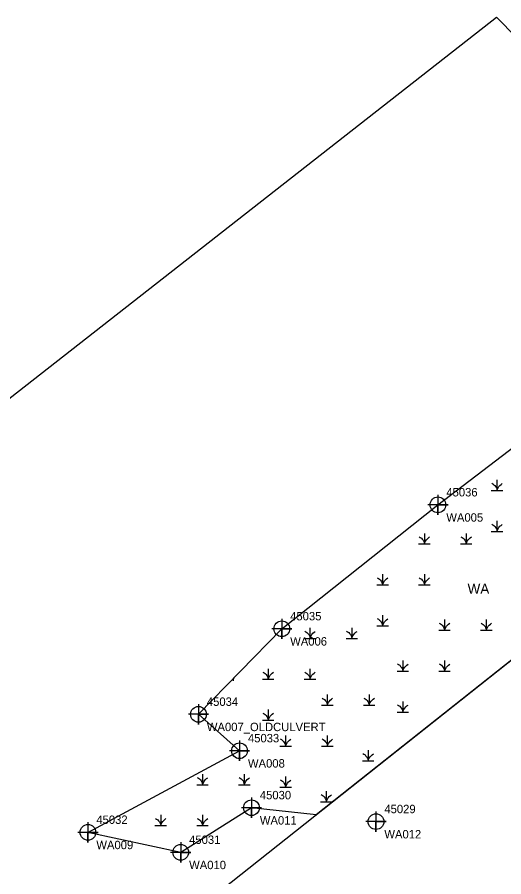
# Model space of a CAD drawing. Extents: x 1503676 to 1665494, y 654328 to 989038.
# Drawn here: x 1577550.8 to 1577695.6, y 654583.6 to 654839 of the extents above; entities that cross this region are included whole.
import ezdxf

# ---------------------------------------------------------------- set-up
doc = ezdxf.new("R2010")
doc.units = 0
for name, color, linetype in [('Default', 7, 'Continuous'), ('Level 14', 7, 'Continuous'), ('Level 17', 7, 'Continuous'), ('Level 2', 7, 'Continuous'), ('Level 25', 7, 'Continuous'), ('Level 28', 7, 'Continuous'), ('Level 3', 7, 'Continuous')]:
    doc.layers.add(name, color=color, linetype=linetype)

msp = doc.modelspace()

# ---------------------------------------------------------------- linework, layer by layer
at = {"layer": 'Default'}
msp.add_lwpolyline([(1577196.91, 654451.02), (1577693.44, 654839.04), (1577801.08, 654729.67), (1577293.27, 654327.76)], close=True, dxfattribs=at)
at = {"layer": 'Level 2'}
for points in [[(1577675.98, 654697.16), (1577675.98, 654691.16), (1577675.98, 654694.16), (1577678.98, 654694.16), (1577672.98, 654694.16)], [(1577629.53, 654660.34), (1577629.53, 654654.34), (1577629.53, 654657.34), (1577632.53, 654657.34), (1577626.53, 654657.34)], [(1577604.75, 654634.93), (1577604.75, 654628.93), (1577604.75, 654631.93), (1577607.75, 654631.93), (1577601.75, 654631.93)], [(1577616.97, 654624.1), (1577616.97, 654618.1), (1577616.97, 654621.1), (1577619.97, 654621.1), (1577613.97, 654621.1)], [(1577620.51, 654607.17), (1577620.51, 654601.17), (1577620.51, 654604.17), (1577623.51, 654604.17), (1577617.51, 654604.17)], [(1577657.55, 654603.05), (1577657.55, 654597.05), (1577657.55, 654600.05), (1577660.55, 654600.05), (1577654.55, 654600.05)], [(1577571.87, 654599.86), (1577571.87, 654593.86), (1577571.87, 654596.86), (1577574.87, 654596.86), (1577568.87, 654596.86)], [(1577599.47, 654593.92), (1577599.47, 654587.92), (1577599.47, 654590.92), (1577602.47, 654590.92), (1577596.47, 654590.92)]]:
    msp.add_lwpolyline(points, dxfattribs=at)
for centre in [(1577675.98, 654694.16), (1577629.53, 654657.34), (1577604.75, 654631.93), (1577616.97, 654621.1), (1577620.51, 654604.17), (1577657.55, 654600.05), (1577571.87, 654596.86), (1577599.47, 654590.92)]:
    msp.add_circle(centre, 2.34, dxfattribs=at)
at = {"layer": 'Level 28'}
for p, q in [((1577691.98, 654700.56), (1577692.33, 654700.37)), ((1577692.33, 654700.37), (1577692.65, 654700.15)), ((1577692.65, 654700.15), (1577692.92, 654699.86)), ((1577693.54, 654701.58), (1577693.54, 654698.42)), ((1577694.14, 654699.61), (1577694.44, 654699.94)), ((1577694.44, 654699.94), (1577694.76, 654700.23)), ((1577694.76, 654700.23), (1577695.11, 654700.5)), ((1577691.84, 654698.42), (1577695.27, 654698.42)), ((1577692.92, 654699.86), (1577693.17, 654699.53)), ((1577693.17, 654699.53), (1577693.36, 654699.18)), ((1577693.36, 654699.18), (1577693.46, 654698.8)), ((1577693.46, 654698.8), (1577693.54, 654698.42)), ((1577693.54, 654698.42), (1577693.71, 654698.83)), ((1577693.71, 654698.83), (1577693.9, 654699.23)), ((1577693.9, 654699.23), (1577694.14, 654699.61)), ((1577691.98, 654688.4), (1577692.33, 654688.21)), ((1577692.33, 654688.21), (1577692.65, 654687.99)), ((1577692.65, 654687.99), (1577692.92, 654687.7)), ((1577692.92, 654687.7), (1577693.17, 654687.37)), ((1577693.17, 654687.37), (1577693.36, 654687.02)), ((1577693.54, 654689.42), (1577693.54, 654686.27)), ((1577693.9, 654687.08), (1577694.14, 654687.45)), ((1577694.14, 654687.45), (1577694.44, 654687.78)), ((1577694.44, 654687.78), (1577694.76, 654688.07)), ((1577694.76, 654688.07), (1577695.11, 654688.34)), ((1577670.38, 654684.67), (1577670.73, 654684.48)), ((1577671.94, 654685.69), (1577671.94, 654682.53)), ((1577673.16, 654684.34), (1577673.51, 654684.61)), ((1577682.81, 654684.67), (1577683.16, 654684.48)), ((1577684.37, 654685.69), (1577684.37, 654682.53)), ((1577685.59, 654684.34), (1577685.94, 654684.61)), ((1577691.84, 654686.27), (1577695.27, 654686.27)), ((1577693.36, 654687.02), (1577693.46, 654686.64)), ((1577693.46, 654686.64), (1577693.54, 654686.27)), ((1577693.54, 654686.27), (1577693.71, 654686.67)), ((1577693.71, 654686.67), (1577693.9, 654687.08)), ((1577670.24, 654682.53), (1577673.67, 654682.53)), ((1577670.73, 654684.48), (1577671.05, 654684.26)), ((1577671.05, 654684.26), (1577671.32, 654683.96)), ((1577671.32, 654683.96), (1577671.57, 654683.64)), ((1577671.57, 654683.64), (1577671.76, 654683.29)), ((1577671.76, 654683.29), (1577671.86, 654682.91)), ((1577671.86, 654682.91), (1577671.94, 654682.53)), ((1577671.94, 654682.53), (1577672.11, 654682.94)), ((1577672.11, 654682.94), (1577672.3, 654683.34)), ((1577672.3, 654683.34), (1577672.54, 654683.72)), ((1577672.54, 654683.72), (1577672.84, 654684.04)), ((1577672.84, 654684.04), (1577673.16, 654684.34)), ((1577682.67, 654682.53), (1577686.1, 654682.53)), ((1577683.16, 654684.48), (1577683.48, 654684.26)), ((1577683.48, 654684.26), (1577683.75, 654683.96)), ((1577683.75, 654683.96), (1577684, 654683.64)), ((1577684, 654683.64), (1577684.18, 654683.29)), ((1577684.18, 654683.29), (1577684.29, 654682.91)), ((1577684.29, 654682.91), (1577684.37, 654682.53)), ((1577684.37, 654682.53), (1577684.54, 654682.94)), ((1577684.54, 654682.94), (1577684.72, 654683.34)), ((1577684.72, 654683.34), (1577684.97, 654683.72)), ((1577684.97, 654683.72), (1577685.26, 654684.04)), ((1577685.26, 654684.04), (1577685.59, 654684.34)), ((1577657.95, 654672.51), (1577658.3, 654672.32)), ((1577658.3, 654672.32), (1577658.62, 654672.1)), ((1577658.62, 654672.1), (1577658.89, 654671.8)), ((1577659.52, 654673.53), (1577659.52, 654670.37)), ((1577660.11, 654671.56), (1577660.41, 654671.89)), ((1577660.41, 654671.89), (1577660.73, 654672.18)), ((1577660.73, 654672.18), (1577661.08, 654672.45)), ((1577670.38, 654672.51), (1577670.73, 654672.32)), ((1577670.73, 654672.32), (1577671.05, 654672.1)), ((1577671.05, 654672.1), (1577671.32, 654671.8)), ((1577671.94, 654673.53), (1577671.94, 654670.37)), ((1577672.54, 654671.56), (1577672.84, 654671.89)), ((1577672.84, 654671.89), (1577673.16, 654672.18)), ((1577673.16, 654672.18), (1577673.51, 654672.45)), ((1577657.81, 654670.37), (1577661.24, 654670.37)), ((1577658.89, 654671.8), (1577659.14, 654671.48)), ((1577659.14, 654671.48), (1577659.33, 654671.13)), ((1577659.33, 654671.13), (1577659.43, 654670.75)), ((1577659.43, 654670.75), (1577659.52, 654670.37)), ((1577659.52, 654670.37), (1577659.68, 654670.78)), ((1577659.68, 654670.78), (1577659.87, 654671.18)), ((1577659.87, 654671.18), (1577660.11, 654671.56)), ((1577670.24, 654670.37), (1577673.67, 654670.37)), ((1577671.32, 654671.8), (1577671.57, 654671.48)), ((1577671.57, 654671.48), (1577671.76, 654671.13)), ((1577671.76, 654671.13), (1577671.86, 654670.75)), ((1577671.86, 654670.75), (1577671.94, 654670.37)), ((1577671.94, 654670.37), (1577672.11, 654670.78)), ((1577672.11, 654670.78), (1577672.3, 654671.18)), ((1577672.3, 654671.18), (1577672.54, 654671.56)), ((1577635.76, 654662.28), (1577635.78, 654662.18)), ((1577635.78, 654662.18), (1577635.85, 654662.36)), ((1577635.78, 654662.3), (1577635.78, 654662.18)), ((1577657.95, 654660.35), (1577658.3, 654660.16)), ((1577658.3, 654660.16), (1577658.62, 654659.94)), ((1577658.62, 654659.94), (1577658.89, 654659.65)), ((1577658.89, 654659.65), (1577659.14, 654659.32)), ((1577659.14, 654659.32), (1577659.33, 654658.97)), ((1577659.52, 654661.37), (1577659.52, 654658.21)), ((1577659.87, 654659.02), (1577660.11, 654659.4)), ((1577660.11, 654659.4), (1577660.41, 654659.73)), ((1577660.41, 654659.73), (1577660.73, 654660.02)), ((1577660.73, 654660.02), (1577661.08, 654660.29)), ((1577677.94, 654660.07), (1577677.94, 654656.91)), ((1577690.37, 654660.07), (1577690.37, 654656.91)), ((1577636.35, 654656.61), (1577636.7, 654656.43)), ((1577637.92, 654657.64), (1577637.92, 654654.48)), ((1577639.13, 654656.29), (1577639.48, 654656.56)), ((1577648.78, 654656.61), (1577649.13, 654656.43)), ((1577650.34, 654657.64), (1577650.34, 654654.48)), ((1577651.56, 654656.29), (1577651.91, 654656.56)), ((1577657.81, 654658.21), (1577661.24, 654658.21)), ((1577659.33, 654658.97), (1577659.43, 654658.59)), ((1577659.43, 654658.59), (1577659.52, 654658.21)), ((1577659.52, 654658.21), (1577659.68, 654658.62)), ((1577659.68, 654658.62), (1577659.87, 654659.02)), ((1577676.24, 654656.91), (1577679.67, 654656.91)), ((1577676.37, 654659.04), (1577676.73, 654658.85)), ((1577676.73, 654658.85), (1577677.05, 654658.63)), ((1577677.05, 654658.63), (1577677.32, 654658.34)), ((1577677.32, 654658.34), (1577677.56, 654658.01)), ((1577677.56, 654658.01), (1577677.75, 654657.66)), ((1577677.75, 654657.66), (1577677.86, 654657.28)), ((1577677.86, 654657.28), (1577677.94, 654656.91)), ((1577677.94, 654656.91), (1577678.1, 654657.31)), ((1577678.1, 654657.31), (1577678.29, 654657.72)), ((1577678.29, 654657.72), (1577678.53, 654658.09)), ((1577678.53, 654658.09), (1577678.83, 654658.42)), ((1577678.83, 654658.42), (1577679.16, 654658.72)), ((1577679.16, 654658.72), (1577679.51, 654658.99)), ((1577688.67, 654656.91), (1577692.1, 654656.91)), ((1577688.8, 654659.04), (1577689.15, 654658.85)), ((1577689.15, 654658.85), (1577689.48, 654658.63)), ((1577689.48, 654658.63), (1577689.75, 654658.34)), ((1577689.75, 654658.34), (1577689.99, 654658.01)), ((1577689.99, 654658.01), (1577690.18, 654657.66)), ((1577690.18, 654657.66), (1577690.29, 654657.28)), ((1577690.29, 654657.28), (1577690.37, 654656.91)), ((1577690.37, 654656.91), (1577690.53, 654657.31)), ((1577690.53, 654657.31), (1577690.72, 654657.72)), ((1577690.72, 654657.72), (1577690.96, 654658.09)), ((1577690.96, 654658.09), (1577691.26, 654658.42)), ((1577691.26, 654658.42), (1577691.58, 654658.72)), ((1577691.58, 654658.72), (1577691.94, 654658.99)), ((1577636.21, 654654.48), (1577639.64, 654654.48)), ((1577636.7, 654656.43), (1577637.02, 654656.21)), ((1577637.02, 654656.21), (1577637.29, 654655.91)), ((1577637.29, 654655.91), (1577637.54, 654655.59)), ((1577637.54, 654655.59), (1577637.73, 654655.24)), ((1577637.73, 654655.24), (1577637.83, 654654.86)), ((1577637.83, 654654.86), (1577637.92, 654654.48)), ((1577637.92, 654654.48), (1577638.08, 654654.89)), ((1577638.08, 654654.89), (1577638.27, 654655.29)), ((1577638.27, 654655.29), (1577638.51, 654655.67)), ((1577638.51, 654655.67), (1577638.81, 654655.99)), ((1577638.81, 654655.99), (1577639.13, 654656.29)), ((1577648.64, 654654.48), (1577652.07, 654654.48)), ((1577649.13, 654656.43), (1577649.45, 654656.21)), ((1577649.45, 654656.21), (1577649.72, 654655.91)), ((1577649.72, 654655.91), (1577649.97, 654655.59)), ((1577649.97, 654655.59), (1577650.16, 654655.24)), ((1577650.16, 654655.24), (1577650.26, 654654.86)), ((1577650.26, 654654.86), (1577650.34, 654654.48)), ((1577650.34, 654654.48), (1577650.51, 654654.89)), ((1577650.51, 654654.89), (1577650.7, 654655.29)), ((1577650.7, 654655.29), (1577650.94, 654655.67)), ((1577650.94, 654655.67), (1577651.24, 654655.99)), ((1577651.24, 654655.99), (1577651.56, 654656.29)), ((1577663.95, 654646.88), (1577664.3, 654646.69)), ((1577664.3, 654646.69), (1577664.62, 654646.48)), ((1577664.62, 654646.48), (1577664.89, 654646.18)), ((1577665.51, 654647.91), (1577665.51, 654644.75)), ((1577666.4, 654646.26), (1577666.73, 654646.56)), ((1577666.73, 654646.56), (1577667.08, 654646.83)), ((1577676.37, 654646.88), (1577676.73, 654646.69)), ((1577676.73, 654646.69), (1577677.05, 654646.48)), ((1577677.05, 654646.48), (1577677.32, 654646.18)), ((1577677.94, 654647.91), (1577677.94, 654644.75)), ((1577678.83, 654646.26), (1577679.16, 654646.56)), ((1577679.16, 654646.56), (1577679.51, 654646.83)), ((1577623.92, 654644.46), (1577624.27, 654644.27)), ((1577624.27, 654644.27), (1577624.6, 654644.05)), ((1577624.6, 654644.05), (1577624.87, 654643.75)), ((1577624.87, 654643.75), (1577625.11, 654643.43)), ((1577625.49, 654645.48), (1577625.49, 654642.32)), ((1577626.08, 654643.51), (1577626.38, 654643.83)), ((1577626.38, 654643.83), (1577626.7, 654644.13)), ((1577626.7, 654644.13), (1577627.05, 654644.4)), ((1577636.35, 654644.46), (1577636.7, 654644.27)), ((1577636.7, 654644.27), (1577637.02, 654644.05)), ((1577637.02, 654644.05), (1577637.29, 654643.75)), ((1577637.29, 654643.75), (1577637.54, 654643.43)), ((1577637.92, 654645.48), (1577637.92, 654642.32)), ((1577638.51, 654643.51), (1577638.81, 654643.83)), ((1577638.81, 654643.83), (1577639.13, 654644.13)), ((1577639.13, 654644.13), (1577639.48, 654644.4)), ((1577663.81, 654644.75), (1577667.24, 654644.75)), ((1577664.89, 654646.18), (1577665.13, 654645.85)), ((1577665.13, 654645.85), (1577665.32, 654645.5)), ((1577665.32, 654645.5), (1577665.43, 654645.13)), ((1577665.43, 654645.13), (1577665.51, 654644.75)), ((1577665.51, 654644.75), (1577665.67, 654645.15)), ((1577665.67, 654645.15), (1577665.86, 654645.56)), ((1577665.86, 654645.56), (1577666.11, 654645.94)), ((1577666.11, 654645.94), (1577666.4, 654646.26)), ((1577676.24, 654644.75), (1577679.67, 654644.75)), ((1577677.32, 654646.18), (1577677.56, 654645.85)), ((1577677.56, 654645.85), (1577677.75, 654645.5)), ((1577677.75, 654645.5), (1577677.86, 654645.13)), ((1577677.86, 654645.13), (1577677.94, 654644.75)), ((1577677.94, 654644.75), (1577678.1, 654645.15)), ((1577678.1, 654645.15), (1577678.29, 654645.56)), ((1577678.29, 654645.56), (1577678.53, 654645.94)), ((1577678.53, 654645.94), (1577678.83, 654646.26)), ((1577614.96, 654642.4), (1577615.06, 654641.91)), ((1577615.06, 654642.51), (1577615.06, 654641.91)), ((1577615.33, 654642.59), (1577615.51, 654642.97)), ((1577623.79, 654642.32), (1577627.21, 654642.32)), ((1577625.11, 654643.43), (1577625.3, 654643.08)), ((1577625.3, 654643.08), (1577625.41, 654642.7)), ((1577625.41, 654642.7), (1577625.49, 654642.32)), ((1577625.49, 654642.32), (1577625.65, 654642.73)), ((1577625.65, 654642.73), (1577625.84, 654643.13)), ((1577625.84, 654643.13), (1577626.08, 654643.51)), ((1577636.21, 654642.32), (1577639.64, 654642.32)), ((1577637.54, 654643.43), (1577637.73, 654643.08)), ((1577637.73, 654643.08), (1577637.83, 654642.7)), ((1577637.83, 654642.7), (1577637.92, 654642.32)), ((1577637.92, 654642.32), (1577638.08, 654642.73)), ((1577638.08, 654642.73), (1577638.27, 654643.13)), ((1577638.27, 654643.13), (1577638.51, 654643.51)), ((1577641.52, 654636.75), (1577641.87, 654636.57)), ((1577641.87, 654636.57), (1577642.19, 654636.35)), ((1577642.19, 654636.35), (1577642.46, 654636.05)), ((1577643.08, 654637.78), (1577643.08, 654634.62)), ((1577643.68, 654635.81), (1577643.97, 654636.13)), ((1577643.97, 654636.13), (1577644.3, 654636.43)), ((1577644.3, 654636.43), (1577644.65, 654636.7)), ((1577653.94, 654636.75), (1577654.3, 654636.57)), ((1577654.3, 654636.57), (1577654.62, 654636.35)), ((1577654.62, 654636.35), (1577654.89, 654636.05)), ((1577655.51, 654637.78), (1577655.51, 654634.62)), ((1577656.1, 654635.81), (1577656.4, 654636.13)), ((1577656.4, 654636.13), (1577656.73, 654636.43)), ((1577656.73, 654636.43), (1577657.08, 654636.7)), ((1577641.38, 654634.62), (1577644.81, 654634.62)), ((1577642.46, 654636.05), (1577642.7, 654635.73)), ((1577642.7, 654635.73), (1577642.89, 654635.38)), ((1577642.89, 654635.38), (1577643, 654635)), ((1577643, 654635), (1577643.08, 654634.62)), ((1577643.08, 654634.62), (1577643.24, 654635.03)), ((1577643.24, 654635.03), (1577643.43, 654635.43)), ((1577643.43, 654635.43), (1577643.68, 654635.81)), ((1577653.81, 654634.62), (1577657.24, 654634.62)), ((1577654.89, 654636.05), (1577655.13, 654635.73)), ((1577655.13, 654635.73), (1577655.32, 654635.38)), ((1577655.32, 654635.38), (1577655.43, 654635)), ((1577655.43, 654635), (1577655.51, 654634.62)), ((1577655.51, 654634.62), (1577655.67, 654635.03)), ((1577655.67, 654635.03), (1577655.86, 654635.43)), ((1577655.86, 654635.43), (1577656.1, 654635.81)), ((1577663.95, 654634.72), (1577664.3, 654634.53)), ((1577664.3, 654634.53), (1577664.62, 654634.32)), ((1577664.62, 654634.32), (1577664.89, 654634.02)), ((1577664.89, 654634.02), (1577665.13, 654633.7)), ((1577665.13, 654633.7), (1577665.32, 654633.34)), ((1577665.51, 654635.75), (1577665.51, 654632.59)), ((1577665.86, 654633.4), (1577666.11, 654633.78)), ((1577666.11, 654633.78), (1577666.4, 654634.1)), ((1577666.4, 654634.1), (1577666.73, 654634.4)), ((1577666.73, 654634.4), (1577667.08, 654634.67)), ((1577623.92, 654632.3), (1577624.27, 654632.11)), ((1577624.27, 654632.11), (1577624.6, 654631.89)), ((1577624.6, 654631.89), (1577624.87, 654631.59)), ((1577624.87, 654631.59), (1577625.11, 654631.27)), ((1577625.11, 654631.27), (1577625.3, 654630.92)), ((1577625.49, 654633.32), (1577625.49, 654630.16)), ((1577625.65, 654630.57), (1577625.84, 654630.97)), ((1577625.84, 654630.97), (1577626.08, 654631.35)), ((1577626.08, 654631.35), (1577626.38, 654631.68)), ((1577626.38, 654631.68), (1577626.7, 654631.97)), ((1577626.7, 654631.97), (1577627.05, 654632.24)), ((1577663.81, 654632.59), (1577667.24, 654632.59)), ((1577665.32, 654633.34), (1577665.43, 654632.97)), ((1577665.43, 654632.97), (1577665.51, 654632.59)), ((1577665.51, 654632.59), (1577665.67, 654632.99)), ((1577665.67, 654632.99), (1577665.86, 654633.4)), ((1577623.79, 654630.16), (1577627.21, 654630.16)), ((1577625.3, 654630.92), (1577625.41, 654630.54)), ((1577625.41, 654630.54), (1577625.49, 654630.16)), ((1577625.49, 654630.16), (1577625.65, 654630.57)), ((1577629.09, 654624.6), (1577629.44, 654624.41)), ((1577629.44, 654624.41), (1577629.76, 654624.19)), ((1577629.76, 654624.19), (1577630.03, 654623.89)), ((1577630.03, 654623.89), (1577630.27, 654623.57)), ((1577630.27, 654623.57), (1577630.46, 654623.22)), ((1577630.65, 654625.62), (1577630.65, 654622.46)), ((1577631, 654623.27), (1577631.25, 654623.65)), ((1577631.25, 654623.65), (1577631.54, 654623.97)), ((1577631.54, 654623.97), (1577631.87, 654624.27)), ((1577631.87, 654624.27), (1577632.22, 654624.54)), ((1577641.52, 654624.6), (1577641.87, 654624.41)), ((1577641.87, 654624.41), (1577642.19, 654624.19)), ((1577642.19, 654624.19), (1577642.46, 654623.89)), ((1577642.46, 654623.89), (1577642.7, 654623.57)), ((1577642.7, 654623.57), (1577642.89, 654623.22)), ((1577643.08, 654625.62), (1577643.08, 654622.46)), ((1577643.43, 654623.27), (1577643.68, 654623.65)), ((1577643.68, 654623.65), (1577643.97, 654623.97)), ((1577643.97, 654623.97), (1577644.3, 654624.27)), ((1577644.3, 654624.27), (1577644.65, 654624.54)), ((1577628.95, 654622.46), (1577632.38, 654622.46)), ((1577630.46, 654623.22), (1577630.57, 654622.84)), ((1577630.57, 654622.84), (1577630.65, 654622.46)), ((1577630.65, 654622.46), (1577630.81, 654622.87)), ((1577630.81, 654622.87), (1577631, 654623.27)), ((1577641.38, 654622.46), (1577644.81, 654622.46)), ((1577642.89, 654623.22), (1577643, 654622.84)), ((1577643, 654622.84), (1577643.08, 654622.46)), ((1577643.08, 654622.46), (1577643.24, 654622.87)), ((1577643.24, 654622.87), (1577643.43, 654623.27)), ((1577655.2, 654621.27), (1577655.2, 654618.11)), ((1577653.63, 654620.24), (1577653.98, 654620.05)), ((1577653.98, 654620.05), (1577654.31, 654619.84)), ((1577654.31, 654619.84), (1577654.58, 654619.54)), ((1577654.58, 654619.54), (1577654.82, 654619.22)), ((1577654.82, 654619.22), (1577655.01, 654618.86)), ((1577655.01, 654618.86), (1577655.12, 654618.49)), ((1577655.12, 654618.49), (1577655.2, 654618.11)), ((1577655.2, 654618.11), (1577655.36, 654618.51)), ((1577655.36, 654618.51), (1577655.55, 654618.92)), ((1577655.55, 654618.92), (1577655.79, 654619.3)), ((1577655.79, 654619.3), (1577656.09, 654619.62)), ((1577656.09, 654619.62), (1577656.41, 654619.92)), ((1577656.41, 654619.92), (1577656.77, 654620.19)), ((1577653.5, 654618.11), (1577656.93, 654618.11)), ((1577604.38, 654613.15), (1577604.73, 654612.96)), ((1577605.94, 654614.18), (1577605.94, 654611.02)), ((1577607.16, 654612.83), (1577607.51, 654613.1)), ((1577616.81, 654613.15), (1577617.16, 654612.96)), ((1577618.37, 654614.18), (1577618.37, 654611.02)), ((1577619.59, 654612.83), (1577619.94, 654613.1)), ((1577630.65, 654613.46), (1577630.65, 654610.3)), ((1577604.24, 654611.02), (1577607.67, 654611.02)), ((1577604.73, 654612.96), (1577605.05, 654612.75)), ((1577605.05, 654612.75), (1577605.32, 654612.45)), ((1577605.32, 654612.45), (1577605.57, 654612.13)), ((1577605.57, 654612.13), (1577605.76, 654611.78)), ((1577605.76, 654611.78), (1577605.86, 654611.4)), ((1577605.86, 654611.4), (1577605.94, 654611.02)), ((1577605.94, 654611.02), (1577606.11, 654611.42)), ((1577606.11, 654611.42), (1577606.3, 654611.83)), ((1577606.3, 654611.83), (1577606.54, 654612.21)), ((1577606.54, 654612.21), (1577606.84, 654612.53)), ((1577606.84, 654612.53), (1577607.16, 654612.83)), ((1577616.67, 654611.02), (1577620.1, 654611.02)), ((1577617.16, 654612.96), (1577617.48, 654612.75)), ((1577617.48, 654612.75), (1577617.75, 654612.45)), ((1577617.75, 654612.45), (1577618, 654612.13)), ((1577618, 654612.13), (1577618.18, 654611.78)), ((1577618.18, 654611.78), (1577618.29, 654611.4)), ((1577618.29, 654611.4), (1577618.37, 654611.02)), ((1577618.37, 654611.02), (1577618.54, 654611.42)), ((1577618.54, 654611.42), (1577618.72, 654611.83)), ((1577618.72, 654611.83), (1577618.97, 654612.21)), ((1577618.97, 654612.21), (1577619.26, 654612.53)), ((1577619.26, 654612.53), (1577619.59, 654612.83)), ((1577629.09, 654612.44), (1577629.44, 654612.25)), ((1577629.44, 654612.25), (1577629.76, 654612.03)), ((1577629.76, 654612.03), (1577630.03, 654611.73)), ((1577630.03, 654611.73), (1577630.27, 654611.41)), ((1577630.27, 654611.41), (1577630.46, 654611.06)), ((1577630.46, 654611.06), (1577630.57, 654610.68)), ((1577630.57, 654610.68), (1577630.65, 654610.3)), ((1577630.65, 654610.3), (1577630.81, 654610.71)), ((1577630.81, 654610.71), (1577631, 654611.11)), ((1577631, 654611.11), (1577631.25, 654611.49)), ((1577631.25, 654611.49), (1577631.54, 654611.82)), ((1577631.54, 654611.82), (1577631.87, 654612.11)), ((1577631.87, 654612.11), (1577632.22, 654612.38)), ((1577628.95, 654610.3), (1577632.38, 654610.3)), ((1577641.2, 654608.08), (1577641.56, 654607.89)), ((1577642.77, 654609.11), (1577642.77, 654605.95)), ((1577643.99, 654607.76), (1577644.34, 654608.03)), ((1577641.07, 654605.95), (1577644.5, 654605.95)), ((1577641.56, 654607.89), (1577641.88, 654607.68)), ((1577641.88, 654607.68), (1577642.15, 654607.38)), ((1577642.15, 654607.38), (1577642.39, 654607.06)), ((1577642.39, 654607.06), (1577642.58, 654606.71)), ((1577642.58, 654606.71), (1577642.69, 654606.33)), ((1577642.69, 654606.33), (1577642.77, 654605.95)), ((1577642.77, 654605.95), (1577642.93, 654606.35)), ((1577642.93, 654606.35), (1577643.12, 654606.76)), ((1577643.12, 654606.76), (1577643.36, 654607.14)), ((1577643.36, 654607.14), (1577643.66, 654607.46)), ((1577643.66, 654607.46), (1577643.99, 654607.76)), ((1577591.95, 654600.99), (1577592.3, 654600.8)), ((1577592.3, 654600.8), (1577592.62, 654600.59)), ((1577592.62, 654600.59), (1577592.89, 654600.29)), ((1577593.52, 654602.02), (1577593.52, 654598.86)), ((1577594.11, 654600.05), (1577594.41, 654600.37)), ((1577594.41, 654600.37), (1577594.73, 654600.67)), ((1577594.73, 654600.67), (1577595.08, 654600.94)), ((1577604.38, 654600.99), (1577604.73, 654600.8)), ((1577604.73, 654600.8), (1577605.05, 654600.59)), ((1577605.05, 654600.59), (1577605.32, 654600.29)), ((1577605.94, 654602.02), (1577605.94, 654598.86)), ((1577606.54, 654600.05), (1577606.84, 654600.37)), ((1577606.84, 654600.37), (1577607.16, 654600.67)), ((1577607.16, 654600.67), (1577607.51, 654600.94)), ((1577591.81, 654598.86), (1577595.24, 654598.86)), ((1577592.89, 654600.29), (1577593.14, 654599.97)), ((1577593.14, 654599.97), (1577593.33, 654599.62)), ((1577593.33, 654599.62), (1577593.43, 654599.24)), ((1577593.43, 654599.24), (1577593.52, 654598.86)), ((1577593.52, 654598.86), (1577593.68, 654599.27)), ((1577593.68, 654599.27), (1577593.87, 654599.67)), ((1577593.87, 654599.67), (1577594.11, 654600.05)), ((1577604.24, 654598.86), (1577607.67, 654598.86)), ((1577605.32, 654600.29), (1577605.57, 654599.97)), ((1577605.57, 654599.97), (1577605.76, 654599.62)), ((1577605.76, 654599.62), (1577605.86, 654599.24)), ((1577605.86, 654599.24), (1577605.94, 654598.86)), ((1577605.94, 654598.86), (1577606.11, 654599.27)), ((1577606.11, 654599.27), (1577606.3, 654599.67)), ((1577606.3, 654599.67), (1577606.54, 654600.05))]:
    msp.add_line(p, q, dxfattribs=at)
at = {"layer": 'Level 3'}
msp.add_lwpolyline([(1577801.08, 654729.67), (1577639.8, 654602.02), (1577620.51, 654604.17), (1577599.47, 654590.92), (1577571.87, 654596.86), (1577616.97, 654621.1), (1577604.75, 654631.93), (1577629.53, 654657.34), (1577675.98, 654694.16), (1577714, 654723.18), (1577731.96, 654708.99), (1577766.48, 654732.06), (1577787.22, 654743.75)], close=True, dxfattribs=at)

# ---------------------------------------------------------------- texts
at = {"layer": 'Level 14'}
for s, p in [('45036', (1577678.48, 654696.66)), ('45035', (1577632.03, 654659.84)), ('45034', (1577607.25, 654634.43)), ('45033', (1577619.47, 654623.6)), ('45030', (1577623.01, 654606.67)), ('45029', (1577660.05, 654602.55)), ('45032', (1577574.37, 654599.36)), ('45031', (1577601.97, 654593.42))]:
    msp.add_text(s, height=2.5, dxfattribs=at).set_placement(p)
at = {"layer": 'Level 17'}
for s, p in [('WA005', (1577678.48, 654689.16)), ('WA006', (1577632.03, 654652.34)), ('WA007_OLDCULVERT', (1577607.25, 654626.93)), ('WA008', (1577619.47, 654616.1)), ('WA011', (1577623.01, 654599.17)), ('WA012', (1577660.05, 654595.05)), ('WA009', (1577574.37, 654591.86)), ('WA010', (1577601.97, 654585.92))]:
    msp.add_text(s, height=2.5, dxfattribs=at).set_placement(p)
at = {"layer": 'Level 25'}
msp.add_text('WA', height=3, dxfattribs=at).set_placement((1577684.8, 654667.73))

doc.saveas('drawing.dxf')
